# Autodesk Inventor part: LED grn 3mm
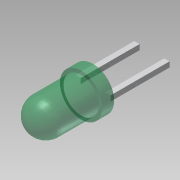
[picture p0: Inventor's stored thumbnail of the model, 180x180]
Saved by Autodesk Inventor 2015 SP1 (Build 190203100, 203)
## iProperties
Created: 2015-05
Part Number: LED grn 3mm
Material: PC/ABS Plastic
Document SubType Name: Modeling
Designer: kazys
Density: 0.357273 g/cm^3
Appearance: Clear - Green 1
Author: kazys
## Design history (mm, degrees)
sketch "Sketch1"
  geometry: C1 r 1.8 at (0, 0); 1 further point
  constraints: 1 centre point, 1 coincident
  dimensions: "d0" = 3.6 diameter of C1
extrude "Extrusion1" new body sketch "Sketch1" distance "d1" = 1; taper "d2" = 0 deg
sketch "Sketch2"
  geometry: L1 (-1.5, 1)-(-1.5, 4); L2 (-1.8, 0)-(1.8, 0) reference; L3 (1.8, 1)-(-1.8, 1) reference; L4 (-1.8, 0)-(1.8, 0) reference; L5 (-1.5, 1)-(0, 1); L6 (1.8, 1)-(-1.8, 1) reference; L7 (0, 5.5)-(0, 1); L8 (0, 0)-(0, -0.856); A1 r 1.5 centre (0, 4) between (0, 5.5) and (-1.5, 4); 1 further point
  constraints: 8 end point, 4 midpoint, 3 vertical, 2 point on circle, 2 point on line, 1 centre point, 1 tangent, 1 vertical alignment
  dimensions: "d3" = 5.5 dimension on A1 L2; "d4" = 3 diameter of A1
revolve "Revolution1" sketch "Sketch2" stored, may be unused: angle "d5" = 90 deg
sketch "Sketch3"
  geometry: L1 (-1.495, 0.225)-(-1.045, 0.225); L2 (-1.045, 0.225)-(-1.045, -0.225); L3 (-1.045, -0.225)-(-1.495, -0.225); L4 (-1.495, -0.225)-(-1.495, 0.225); L5 (1.045, 0.225)-(1.495, 0.225); L6 (1.495, 0.225)-(1.495, -0.225); L7 (1.495, -0.225)-(1.045, -0.225); L8 (1.045, -0.225)-(1.045, 0.225); L9 (-1.495, 0.225)-(-1.045, -0.225); L10 (1.045, 0.225)-(1.495, -0.225); L11 (-1.27, 0)-(1.27, 0); 2 further points
  constraints: 22 end point, 5 parallel, 3 horizontal, 3 midpoint, 2 horizontal alignment, 2 perpendicular, 2 point on line, 1 coincident
  dimensions: "d6" = 2.54 distance of L11.end L11.start; "d7" = 0.45 distance of L3.end L1.start; "d8" = 0.45 distance of L1.start L1.end; "d9" = 0.45 distance of L5.start L5.end (derived)
extrude "Extrusion2" join sketch "Sketch3" distance "d10" = 5; taper "d11" = 0 deg
body "Solid1"
node "Projected Loop1"
